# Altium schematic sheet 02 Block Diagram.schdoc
size 400 x 277 mm; Device: default420x297; Symbol: default420x297; Name: default420x297; Size: "A3"; Id: /; File: 02 Block Diagram; Sheet: /
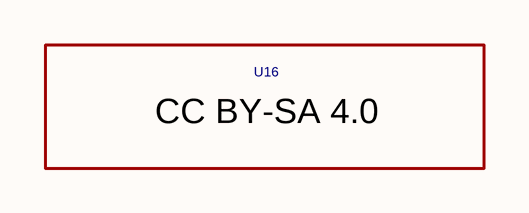
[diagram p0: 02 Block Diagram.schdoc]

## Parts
U16  Misc_LOGO_CC_BY-SA_4.0  [Misc:LOGO_CC_BY-SA_4.0]  (value not drawn)

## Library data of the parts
U16 = Misc_LOGO_CC_BY-SA_4.0: UniqueId: ca4d2b64b6ec8380; AddInBom: yes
